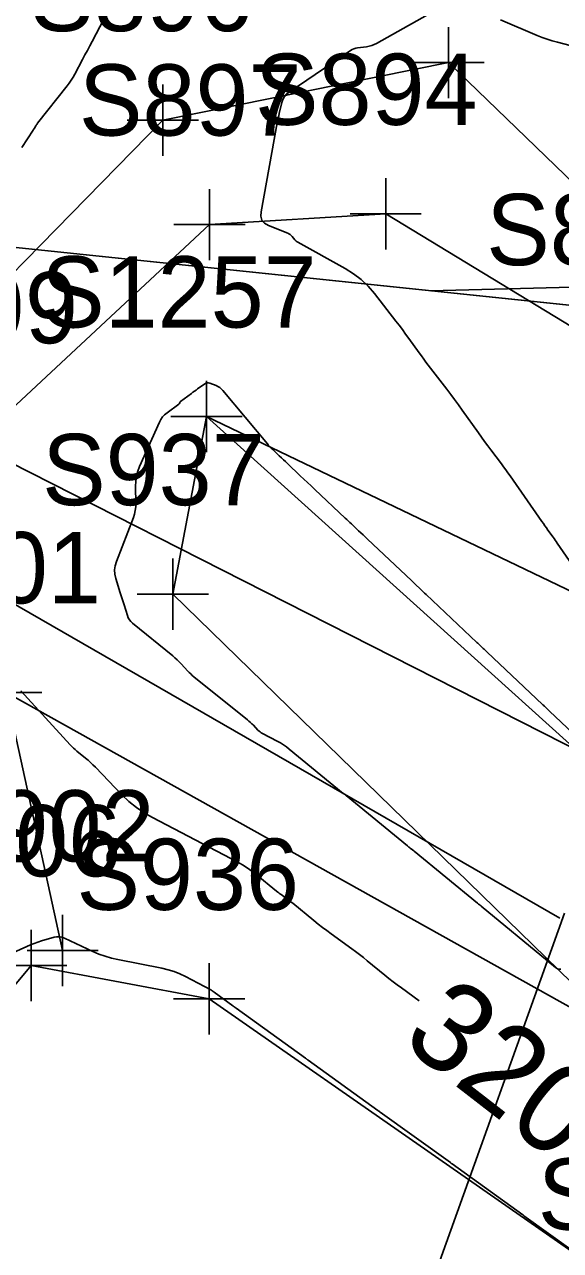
# Model space of a CAD drawing. Extents: x 816928 to 825690, y 436959 to 448212.
# Drawn here: x 818777 to 818807.1, y 444544.8 to 444613.7 of the extents above; entities that cross this region are included whole.
import ezdxf

# ---------------------------------------------------------------- set-up
doc = ezdxf.new("R2010")
doc.units = 0
for name, color, linetype in [('SURVEY - CONTOURS - Index with Text', 7, 'Continuous'), ('SURVEY - CONTOURS - Intermediate with optional Text', 7, 'Continuous'), ('SURVEY - DRAINAGE - Natural Features', 7, 'Continuous'), ('SURVEY - DRAINAGE - Natural Features - Points - Locators', 7, 'Continuous'), ('SURVEY - DRAINAGE - Natural Features - Points - Numbers', 7, 'Continuous'), ('SURVEY - DTM - Breaklines', 7, 'Continuous'), ('SURVEY - DTM - Breaklines - Points - Locators', 7, 'Continuous'), ('SURVEY - DTM - Breaklines - Points - Numbers', 7, 'Continuous'), ('SURVEY - PROPERTY - Parcels', 7, 'Continuous'), ('SURVEY - PROPERTY - Property Lines', 7, 'Continuous'), ('SURVEY - PROPERTY - Property Lines Text', 7, 'Continuous'), ('SURVEY - PROPERTY - ROW Lines Text', 7, 'Continuous'), ('SURVEY - PROPERTY - Station and Offset Flags', 7, 'Continuous')]:
    doc.layers.add(name, color=color, linetype=linetype)

msp = doc.modelspace()

# ---------------------------------------------------------------- linework, layer by layer
at = {"layer": 'SURVEY - CONTOURS - Index with Text'}
for points in [[(818800.519, 444614.731), (818796.768, 444612.616), (818796.632, 444612.548), (818796.492, 444612.494), (818796.346, 444612.454), (818796.197, 444612.428), (818795.699, 444612.367), (818795.595, 444612.348), (818795.495, 444612.317), (818795.4, 444612.275), (818795.309, 444612.221), (818791.855, 444609.883), (818791.71, 444609.764), (818791.593, 444609.627), (818791.506, 444609.469), (818791.448, 444609.291), (818791.304, 444608.678), (818791.274, 444608.546), (818791.246, 444608.414), (818791.219, 444608.282), (818791.194, 444608.149), (818790.281, 444603.162), (818790.269, 444602.906), (818790.335, 444602.693), (818790.48, 444602.522), (818790.702, 444602.395), (818791.779, 444601.957), (818791.848, 444601.924), (818791.911, 444601.884), (818791.969, 444601.836), (818792.021, 444601.781), (818792.182, 444601.587), (818792.218, 444601.548), (818792.257, 444601.512), (818792.3, 444601.48), (818792.345, 444601.452), (818795.008, 444599.974), (818795.471, 444599.686), (818795.898, 444599.356), (818796.289, 444598.985), (818796.645, 444598.572), (818797.845, 444597.029), (818798.031, 444596.787), (818798.215, 444596.543), (818798.397, 444596.297), (818798.576, 444596.05), (818799.158, 444595.238), (818799.283, 444595.065), (818799.41, 444594.893), (818799.538, 444594.722), (818799.668, 444594.552), (818800.709, 444593.199), (818800.93, 444592.908), (818801.149, 444592.615), (818801.364, 444592.32), (818801.577, 444592.022), (818802.479, 444590.746), (818802.651, 444590.504), (818802.826, 444590.263), (818803.003, 444590.024), (818803.182, 444589.787), (818803.771, 444589.013), (818803.896, 444588.847), (818804.02, 444588.679), (818804.142, 444588.51), (818804.261, 444588.34), (818806.042, 444585.778), (818806.127, 444585.657), (818806.213, 444585.535), (818806.299, 444585.414), (818806.386, 444585.294), (818806.671, 444584.901), (818806.732, 444584.817), (818806.792, 444584.732), (818806.852, 444584.647), (818806.911, 444584.562), (818809.266, 444581.142)], [(818808.275, 444612.336), (818806.92, 444612.681), (818806.631, 444612.76), (818806.346, 444612.851), (818806.065, 444612.951), (818805.788, 444613.063), (818803.728, 444613.938)], [(818799.156, 444558.868), (818798.162, 444559.583), (818797.926, 444559.756), (818797.692, 444559.932), (818797.462, 444560.113), (818797.235, 444560.297), (818796.242, 444561.116), (818796.028, 444561.29), (818795.811, 444561.46), (818795.591, 444561.626), (818795.369, 444561.789), (818794.213, 444562.621), (818793.966, 444562.802), (818793.723, 444562.986), (818793.483, 444563.174), (818793.245, 444563.366), (818792.062, 444564.338), (818791.974, 444564.409), (818791.885, 444564.478), (818791.795, 444564.547), (818791.704, 444564.613), (818791.405, 444564.829), (818791.341, 444564.876), (818791.278, 444564.923), (818791.216, 444564.972), (818791.154, 444565.022), (818790.017, 444565.955), (818789.769, 444566.148), (818789.512, 444566.328), (818789.246, 444566.495), (818788.971, 444566.647), (818784.192, 444569.146), (818783.724, 444569.415), (818783.282, 444569.719), (818782.866, 444570.058), (818782.477, 444570.432), (818780.981, 444571.985), (818780.848, 444572.119), (818780.712, 444572.248), (818780.571, 444572.373), (818780.426, 444572.493), (818779.946, 444572.879), (818779.845, 444572.964), (818779.747, 444573.052), (818779.653, 444573.144), (818779.562, 444573.24), (818776.8, 444576.265)]]:
    msp.add_lwpolyline(points, dxfattribs=at)
at = {"layer": 'SURVEY - CONTOURS - Intermediate with optional Text'}
for points in [[(818781.462, 444613.98), (818780.8, 444612.729), (818780.666, 444612.476), (818780.533, 444612.224), (818780.399, 444611.971), (818780.266, 444611.719), (818779.829, 444610.894), (818779.732, 444610.72), (818779.627, 444610.551), (818779.515, 444610.386), (818779.395, 444610.227), (818777.743, 444608.133), (818777.715, 444608.096), (818777.688, 444608.06), (818777.663, 444608.022), (818777.637, 444607.984), (818777.557, 444607.859), (818777.54, 444607.832), (818777.523, 444607.805), (818777.505, 444607.778), (818777.488, 444607.751), (818776.859, 444606.77)], [(818809.741, 444572.045), (818806.48, 444575.126), (818806.44, 444575.164), (818806.4, 444575.202), (818806.36, 444575.24), (818806.319, 444575.278), (818806.188, 444575.402), (818806.16, 444575.428), (818806.132, 444575.455), (818806.103, 444575.481), (818806.075, 444575.508), (818802.976, 444578.435), (818802.919, 444578.489), (818802.862, 444578.543), (818802.805, 444578.597), (818802.748, 444578.651), (818802.562, 444578.826), (818802.522, 444578.864), (818802.482, 444578.902), (818802.442, 444578.939), (818802.403, 444578.977), (818799.543, 444581.678), (818799.461, 444581.755), (818799.379, 444581.833), (818799.297, 444581.91), (818799.216, 444581.987), (818798.948, 444582.24), (818798.89, 444582.295), (818798.833, 444582.349), (818798.776, 444582.403), (818798.718, 444582.457), (818796.251, 444584.788), (818796.128, 444584.904), (818796.005, 444585.02), (818795.881, 444585.137), (818795.758, 444585.253), (818795.356, 444585.633), (818795.27, 444585.714), (818795.184, 444585.796), (818795.098, 444585.877), (818795.012, 444585.958), (818793.301, 444587.574), (818793.097, 444587.767), (818792.893, 444587.959), (818792.69, 444588.152), (818792.486, 444588.344), (818791.762, 444589.028), (818791.648, 444589.135), (818791.535, 444589.243), (818791.421, 444589.35), (818791.307, 444589.457), (818790.936, 444589.808), (818790.857, 444589.885), (818790.781, 444589.963), (818790.708, 444590.044), (818790.636, 444590.127), (818788.128, 444593.13), (818788.049, 444593.214), (818787.961, 444593.287), (818787.865, 444593.349), (818787.76, 444593.399), (818787.405, 444593.543), (818787.33, 444593.564), (818787.257, 444593.565), (818787.187, 444593.547), (818787.12, 444593.508), (818786.719, 444593.215), (818786.633, 444593.152), (818786.547, 444593.089), (818786.461, 444593.026), (818786.375, 444592.963), (818785.76, 444592.513), (818785.746, 444592.501), (818785.734, 444592.488), (818785.725, 444592.473), (818785.717, 444592.457), (818785.696, 444592.401), (818785.691, 444592.39), (818785.685, 444592.38), (818785.676, 444592.37), (818785.667, 444592.362), (818785.003, 444591.878), (818784.87, 444591.767), (818784.754, 444591.642), (818784.656, 444591.503), (818784.575, 444591.349), (818783.463, 444588.867), (818783.359, 444588.597), (818783.287, 444588.32), (818783.246, 444588.037), (818783.236, 444587.747), (818783.256, 444586.791), (818783.25, 444586.588), (818783.225, 444586.388), (818783.181, 444586.192), (818783.116, 444585.999), (818782.161, 444583.531), (818782.09, 444583.293), (818782.062, 444583.053), (818782.075, 444582.813), (818782.13, 444582.57), (818782.38, 444581.777), (818782.433, 444581.607), (818782.487, 444581.437), (818782.54, 444581.267), (818782.594, 444581.097), (818782.783, 444580.495), (818782.832, 444580.371), (818782.896, 444580.259), (818782.977, 444580.157), (818783.074, 444580.066), (818785.323, 444578.234), (818785.45, 444578.127), (818785.572, 444578.015), (818785.691, 444577.899), (818785.805, 444577.779), (818786.17, 444577.378), (818786.25, 444577.294), (818786.333, 444577.213), (818786.419, 444577.135), (818786.508, 444577.061), (818789.514, 444574.643), (818789.602, 444574.569), (818789.687, 444574.494), (818789.77, 444574.415), (818789.851, 444574.334), (818790.11, 444574.064), (818790.168, 444574.009), (818790.229, 444573.959), (818790.295, 444573.914), (818790.364, 444573.874), (818791.195, 444573.44), (818791.37, 444573.342), (818791.54, 444573.236), (818791.704, 444573.122), (818791.862, 444572.999), (818794.9, 444570.505), (818794.915, 444570.493), (818794.93, 444570.481), (818794.945, 444570.47), (818794.96, 444570.458), (818795.011, 444570.422), (818795.022, 444570.414), (818795.032, 444570.406), (818795.043, 444570.398), (818795.053, 444570.389), (818798.503, 444567.555), (818798.54, 444567.525), (818798.577, 444567.496), (818798.615, 444567.467), (818798.653, 444567.439), (818798.779, 444567.349), (818798.806, 444567.329), (818798.832, 444567.309), (818798.858, 444567.289), (818798.884, 444567.268), (818802.433, 444564.34), (818802.454, 444564.324), (818802.475, 444564.307), (818802.496, 444564.292), (818802.517, 444564.276), (818802.587, 444564.226), (818802.602, 444564.215), (818802.617, 444564.204), (818802.631, 444564.192), (818802.645, 444564.18), (818806.356, 444561.107), (818806.359, 444561.104), (818806.362, 444561.102), (818806.366, 444561.099), (818806.369, 444561.097), (818806.379, 444561.09), (818806.381, 444561.088), (818806.383, 444561.087), (818806.385, 444561.085), (818806.388, 444561.083), (818806.818, 444560.725), (818806.913, 444560.663), (818807.012, 444560.633), (818807.115, 444560.634)], [(818776.186, 444561.486), (818777.135, 444561.916), (818777.339, 444562.004), (818777.546, 444562.085), (818777.756, 444562.158), (818777.968, 444562.225), (818778.666, 444562.429), (818778.814, 444562.46), (818778.961, 444562.462), (818779.105, 444562.437), (818779.247, 444562.384), (818780.832, 444561.639), (818781.175, 444561.49), (818781.526, 444561.363), (818781.883, 444561.257), (818782.248, 444561.174), (818784.718, 444560.689), (818785.062, 444560.608), (818785.397, 444560.504), (818785.724, 444560.376), (818786.042, 444560.223), (818787.468, 444559.478), (818787.488, 444559.467), (818787.507, 444559.455), (818787.525, 444559.442), (818787.543, 444559.428), (818787.599, 444559.382), (818787.611, 444559.372), (818787.624, 444559.362), (818787.636, 444559.353), (818787.649, 444559.344), (818788.706, 444558.582), (818788.724, 444558.569), (818788.742, 444558.556), (818788.759, 444558.542), (818788.777, 444558.528), (818788.834, 444558.481), (818788.846, 444558.471), (818788.858, 444558.462), (818788.871, 444558.452), (818788.883, 444558.443), (818792.77, 444555.646), (818792.785, 444555.635), (818792.8, 444555.623), (818792.815, 444555.612), (818792.83, 444555.6), (818792.878, 444555.56), (818792.889, 444555.551), (818792.899, 444555.543), (818792.91, 444555.535), (818792.921, 444555.527), (818796.837, 444552.711), (818796.849, 444552.702), (818796.862, 444552.693), (818796.874, 444552.683), (818796.886, 444552.673), (818796.925, 444552.641), (818796.934, 444552.634), (818796.942, 444552.627), (818796.951, 444552.621), (818796.96, 444552.614), (818800.907, 444549.778), (818800.916, 444549.771), (818800.926, 444549.764), (818800.935, 444549.757), (818800.944, 444549.749), (818800.974, 444549.725), (818800.98, 444549.72), (818800.986, 444549.715), (818800.993, 444549.71), (818801, 444549.705), (818804.981, 444546.847), (818804.987, 444546.842), (818804.993, 444546.838), (818804.999, 444546.833), (818805.005, 444546.828), (818805.024, 444546.812), (818805.028, 444546.809), (818805.033, 444546.805), (818805.037, 444546.802), (818805.041, 444546.799), (818809.059, 444543.917)]]:
    msp.add_lwpolyline(points, dxfattribs=at)
at = {"layer": 'SURVEY - DRAINAGE - Natural Features'}
msp.add_lwpolyline([(818777.383, 444560.851), (818753.523, 444532.2), (818759.523, 444493.046), (818756.761, 444447.133), (818768.088, 444439.021), (818793.285, 444450.363), (818820.069, 444476.929), (818844.694, 444508.111), (818826.35, 444526.757), (818813.149, 444541.013), (818787.365, 444558.968), (818777.383, 444560.851)], dxfattribs=at)
at = {"layer": 'SURVEY - DRAINAGE - Natural Features - Points - Locators'}
for p, q in [((818777.383, 444562.851), (818777.383, 444558.851)), ((818787.365, 444560.968), (818787.365, 444556.968)), ((818779.383, 444560.851), (818775.383, 444560.851)), ((818789.365, 444558.968), (818785.365, 444558.968))]:
    msp.add_line(p, q, dxfattribs=at)
at = {"layer": 'SURVEY - DTM - Breaklines'}
for points in [[(818815.517, 444597.331), (818800.802, 444611.533), (818784.771, 444608.304), (818768.494, 444591.687), (818772.067, 444574.019), (818769.794, 444562.481)], [(818810.258, 444595.165), (818797.277, 444603.039), (818787.394, 444602.438), (818774.865, 444590.78), (818775.978, 444576.18), (818779.146, 444561.687)], [(818785.328, 444581.689), (818787.221, 444591.663), (818822.442, 444559.897), (818859.115, 444521.341), (818881.638, 444497.056), (818880.209, 444488.725), (818869.164, 444484.787), (818860.033, 444487.517), (818824.558, 444451.586)], [(818787.221, 444591.663), (818835.836, 444568.351), (818864.176, 444541.66), (818882.796, 444525.443), (818889.803, 444518.206), (818893.357, 444505.151), (818891.93, 444478.554), (818884.078, 444471.852), (818868.468, 444473.818), (818836.244, 444442.278)], [(818735.804, 444428.835), (818742.519, 444435.26), (818765.207, 444431.593), (818789.97, 444434.668), (818804.735, 444448.966), (818830.474, 444474.158), (818856.836, 444500.282), (818855.207, 444514.52), (818824.313, 444543.706), (818785.328, 444581.689)]]:
    msp.add_lwpolyline(points, dxfattribs=at)
at = {"layer": 'SURVEY - DTM - Breaklines - Points - Locators'}
for p, q in [((818800.802, 444613.533), (818800.802, 444609.533)), ((818802.802, 444611.533), (818798.802, 444611.533)), ((818784.771, 444610.304), (818784.771, 444606.304)), ((818786.771, 444608.304), (818782.771, 444608.304)), ((818797.277, 444605.039), (818797.277, 444601.039)), ((818787.394, 444604.438), (818787.394, 444600.438)), ((818799.277, 444603.039), (818795.277, 444603.039)), ((818789.394, 444602.438), (818785.394, 444602.438)), ((818787.221, 444593.663), (818787.221, 444589.663)), ((818789.221, 444591.663), (818785.221, 444591.663)), ((818785.328, 444583.689), (818785.328, 444579.689)), ((818787.328, 444581.689), (818783.328, 444581.689)), ((818777.978, 444576.18), (818773.978, 444576.18)), ((818779.146, 444563.687), (818779.146, 444559.687)), ((818781.146, 444561.687), (818777.146, 444561.687))]:
    msp.add_line(p, q, dxfattribs=at)
at = {"layer": 'SURVEY - PROPERTY - Parcels'}
for p, q in [((818853.355, 444593.137), (818746.205, 444604.32)), ((818746.205, 444604.32), (818853.355, 444593.137)), ((819226.308, 444324.647), (818742.759, 444594.722))]:
    msp.add_line(p, q, dxfattribs=at)
at = {"layer": 'SURVEY - PROPERTY - Property Lines'}
for p, q in [((818746.205, 444604.32), (818853.355, 444593.137)), ((818742.759, 444594.722), (819226.308, 444324.647))]:
    msp.add_line(p, q, dxfattribs=at)
at = {"layer": 'SURVEY - PROPERTY - Property Lines Text'}
msp.add_lwpolyline([(818922.822, 444601.901), (818799.78, 444598.728)], dxfattribs=at)
at = {"layer": 'SURVEY - PROPERTY - ROW Lines Text'}
msp.add_line((818807.321, 444563.776), (818782.9, 444495.773), dxfattribs=at)
msp.add_lwpolyline([(818807.054, 444563.509), (818744.482, 444599.521)], dxfattribs=at)
at = {"layer": 'SURVEY - PROPERTY - Station and Offset Flags'}
msp.add_lwpolyline([(818846.74, 444553.26), (818746.205, 444604.32)], dxfattribs=at)

# ---------------------------------------------------------------- texts
at = {"layer": 'SURVEY - CONTOURS - Index with Text'}
msp.add_text('320', height=5, rotation=322.23307, dxfattribs=at).set_placement((818798.042, 444556.531))
at = {"layer": 'SURVEY - DRAINAGE - Natural Features - Points - Numbers'}
for s, p in [('S906', (818769.937, 444565.851)), ('S936', (818779.919, 444563.968)), ('S934', (818805.813, 444546.013))]:
    msp.add_text(s, height=4, dxfattribs=at).set_placement(p)
at = {"layer": 'SURVEY - DTM - Breaklines - Points - Numbers'}
for s, p in [('S896', (818777.325, 444613.304)), ('S894', (818789.941, 444608.039)), ('S897', (818780.058, 444607.438)), ('S893', (818802.922, 444600.165)), ('S1257', (818777.934, 444596.663)), ('S899', (818767.514, 444595.78)), ('S937', (818777.992, 444586.689)), ('S901', (818768.799, 444581.18)), ('S902', (818771.81, 444566.687))]:
    msp.add_text(s, height=4, dxfattribs=at).set_placement(p)

doc.saveas('drawing.dxf')
